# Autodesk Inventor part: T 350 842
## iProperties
Company: Mayer & Müller AG Schaltgeräte
Created: 2006-10
Part Number: T 350 842
Material: 2.0060.30
Document SubType Name: Sheet Metal
Designer: I.Baliuc
Manufacturer: Standard
Standards Organization: Custom
Description: Vorkontaktschwert
Density: 8.94 g/cm^3
Sheet Metal Rule: Standard
HalbzeugNorm: DIN 1759
Abmessung: 45 x 4 - 55,1
Author: T.Messerschmitt
Keywords: 267145
Revision Number: 350842
Comments: Variant - C
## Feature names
1. Grobblech1
